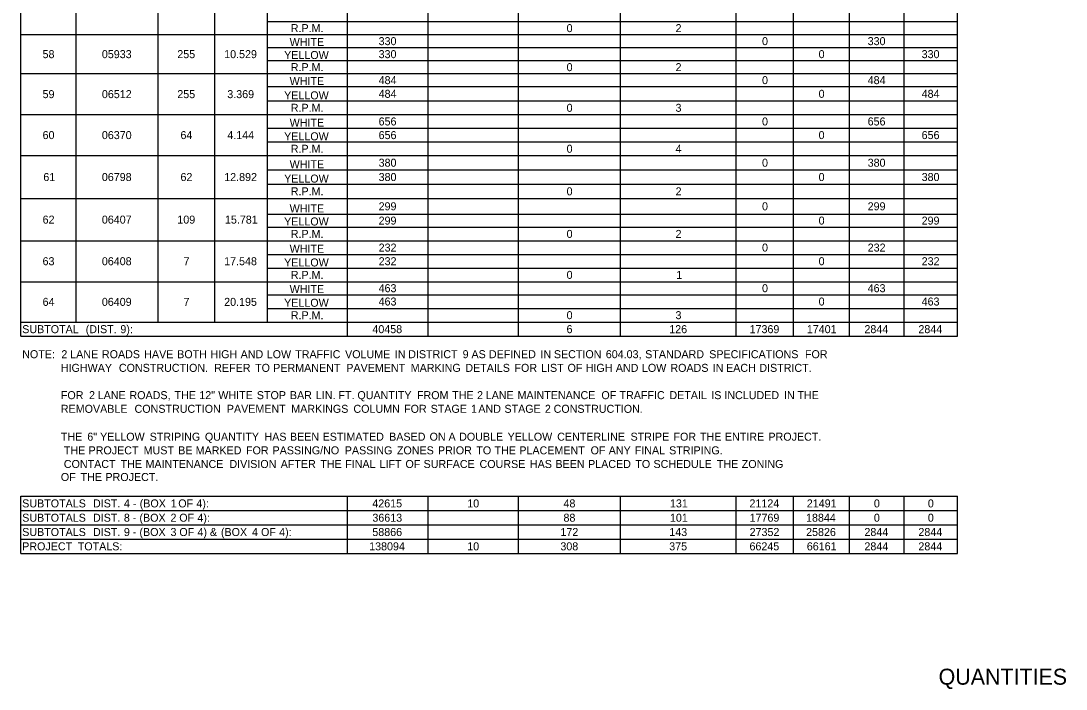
# Model space of a CAD drawing. Extents: x 544420 to 1930787, y -1947044 to 596640.
# Drawn here: x 550705 to 551489, y -1947044 to -1946543 of the extents above; entities that cross this region are included whole.
import ezdxf

# ---------------------------------------------------------------- set-up
doc = ezdxf.new("R2010")
doc.units = 0
doc.layers.add('Default', color=7, linetype='Continuous')
doc.layers.add('R_Annotation', color=7, linetype='Continuous')

msp = doc.modelspace()

# ---------------------------------------------------------------- linework, layer by layer
at = {"layer": 'Default'}
for p, q in [((550705.2, -1946779.72), (550705.2, -1946251.27)), ((550746.64, -1946769), (550746.64, -1946251.27)), ((550808.07, -1946769), (550808.07, -1946251.27)), ((550850.48, -1946769), (550850.48, -1946251.27)), ((550889.97, -1946769), (550889.97, -1946251.27)), ((550949.93, -1946779.72), (550949.93, -1946251.27)), ((551010.38, -1946779.72), (551010.38, -1946251.27)), ((551078.14, -1946779.72), (551078.14, -1946251.27)), ((551241.45, -1946779.72), (551241.45, -1946251.27)), ((551326.28, -1946779.72), (551326.28, -1946251.27)), ((551407.2, -1946779.72), (551407.2, -1946251.27)), ((551154.68, -1946779.72), (551154.68, -1946319.52)), ((551284.35, -1946779.72), (551284.35, -1946319.52)), ((551367.23, -1946779.72), (551367.23, -1946319.52)), ((550889.97, -1946543.77), (551407.2, -1946543.77)), ((550705.2, -1946553.52), (551407.2, -1946553.52)), ((550889.97, -1946563.27), (551407.2, -1946563.27)), ((550889.97, -1946573.02), (551407.2, -1946573.02)), ((550705.2, -1946582.77), (551407.2, -1946582.77)), ((550889.97, -1946592.52), (551407.2, -1946592.52)), ((550889.97, -1946603.25), (551407.2, -1946603.25)), ((550705.2, -1946613.49), (551407.2, -1946613.49)), ((550889.97, -1946623.72), (551407.2, -1946623.72)), ((550889.97, -1946633.96), (551407.2, -1946633.96)), ((550705.2, -1946644.2), (551407.2, -1946644.2)), ((550889.97, -1946654.92), (551407.2, -1946654.92)), ((550889.97, -1946665.65), (551407.2, -1946665.65)), ((550705.2, -1946676.37), (551407.2, -1946676.37)), ((550808.07, -1946769), (550808.07, -1946676.37)), ((550850.48, -1946769), (550850.48, -1946676.37)), ((550889.97, -1946769), (550889.97, -1946676.37)), ((550889.97, -1946688.07), (551407.2, -1946688.07)), ((550889.97, -1946697.82), (551407.2, -1946697.82)), ((550705.2, -1946708.06), (551407.2, -1946708.06)), ((550889.97, -1946718.3), (551407.2, -1946718.3)), ((550889.97, -1946728.54), (551407.2, -1946728.54)), ((550705.2, -1946738.77), (551407.2, -1946738.77)), ((550889.97, -1946748.52), (551407.2, -1946748.52)), ((550889.97, -1946758.76), (551407.2, -1946758.76)), ((550705.2, -1946769), (551407.2, -1946769)), ((550949.93, -1946779.72), (550949.93, -1946769)), ((551010.38, -1946779.72), (551010.38, -1946769)), ((551078.14, -1946779.72), (551078.14, -1946769)), ((551154.68, -1946779.72), (551154.68, -1946769)), ((551241.45, -1946779.72), (551241.45, -1946769)), ((551284.35, -1946779.72), (551284.35, -1946769)), ((551326.28, -1946779.72), (551326.28, -1946769)), ((551367.23, -1946779.72), (551367.23, -1946769)), ((550705.2, -1946779.72), (551407.2, -1946779.72)), ((550705.2, -1946899.65), (551407.2, -1946899.65)), ((550705.2, -1946942.55), (550705.2, -1946899.65)), ((550949.93, -1946942.55), (550949.93, -1946899.65)), ((550949.93, -1946942.55), (550949.93, -1946899.65)), ((551010.38, -1946942.55), (551010.38, -1946899.65)), ((551078.14, -1946942.55), (551078.14, -1946899.65)), ((551154.68, -1946942.55), (551154.68, -1946899.65)), ((551241.45, -1946942.55), (551241.45, -1946899.65)), ((551284.35, -1946942.55), (551284.35, -1946899.65)), ((551326.28, -1946942.55), (551326.28, -1946899.65)), ((551367.23, -1946942.55), (551367.23, -1946899.65)), ((551407.2, -1946942.55), (551407.2, -1946899.65)), ((550705.2, -1946910.37), (551407.2, -1946910.37)), ((550705.2, -1946921.1), (551407.2, -1946921.1)), ((550705.2, -1946931.82), (551407.2, -1946931.82)), ((550705.2, -1946942.55), (551407.2, -1946942.55))]:
    msp.add_line(p, q, dxfattribs=at)

# ---------------------------------------------------------------- texts
for s, p in [('R.P.M.', (550907.51, -1946551.65)), ('0', (551114.28, -1946551.65)), ('2', (551195.96, -1946551.65)), ('WHITE', (550906.67, -1946562.07)), ('330', (550973.36, -1946561.4)), ('0', (551260.77, -1946561.4)), ('330', (551339.96, -1946561.4)), ('58', (550721.45, -1946571.15)), ('05933', (550765.89, -1946571.15)), ('255', (550822.45, -1946571.15)), ('10.529', (550857.59, -1946571.15)), ('YELLOW', (550902.53, -1946571.82)), ('330', (550973.36, -1946571.15)), ('0', (551303.19, -1946571.15)), ('330', (551380.43, -1946571.15)), ('R.P.M.', (550907.51, -1946580.9)), ('0', (551114.28, -1946580.9)), ('2', (551195.96, -1946580.9)), ('WHITE', (550906.67, -1946591.32)), ('484', (550973.37, -1946590.65)), ('0', (551260.77, -1946590.65)), ('484', (551339.97, -1946590.65)), ('59', (550721.45, -1946601.13)), ('06512', (550765.92, -1946601.13)), ('255', (550822.45, -1946601.13)), ('3.369', (550859.92, -1946601.13)), ('YELLOW', (550902.53, -1946602.05)), ('484', (550973.37, -1946600.89)), ('0', (551303.19, -1946600.89)), ('484', (551380.43, -1946600.89)), ('R.P.M.', (550907.51, -1946611.37)), ('0', (551114.28, -1946611.37)), ('3', (551195.93, -1946611.37)), ('WHITE', (550906.67, -1946622.52)), ('656', (550973.35, -1946621.61)), ('0', (551260.77, -1946621.61)), ('656', (551339.95, -1946621.61)), ('60', (550721.46, -1946631.84)), ('06370', (550765.9, -1946631.84)), ('64', (550824.82, -1946631.84)), ('4.144', (550859.94, -1946631.84)), ('YELLOW', (550902.53, -1946632.76)), ('656', (550973.35, -1946631.84)), ('0', (551303.19, -1946631.84)), ('656', (551380.42, -1946631.84)), ('R.P.M.', (550907.51, -1946642.08)), ('0', (551114.28, -1946642.08)), ('4', (551195.94, -1946642.08)), ('WHITE', (550906.67, -1946653.72)), ('380', (550973.36, -1946652.56)), ('0', (551260.77, -1946652.56)), ('380', (551339.96, -1946652.56)), ('61', (550722.03, -1946663.29)), ('06798', (550765.89, -1946663.29)), ('62', (550824.83, -1946663.29)), ('12.892', (550857.63, -1946663.29)), ('YELLOW', (550902.53, -1946664.45)), ('380', (550973.36, -1946663.29)), ('0', (551303.19, -1946663.29)), ('380', (551380.43, -1946663.29)), ('R.P.M.', (550907.51, -1946674.01)), ('0', (551114.28, -1946674.01)), ('2', (551195.96, -1946674.01)), ('WHITE', (550906.67, -1946686.87)), ('299', (550973.35, -1946685.22)), ('0', (551260.77, -1946685.22)), ('299', (551339.95, -1946685.22)), ('62', (550721.48, -1946695.22)), ('06407', (550765.89, -1946695.22)), ('109', (550822.47, -1946695.22)), ('15.781', (550858.18, -1946695.22)), ('YELLOW', (550902.53, -1946696.62)), ('299', (550973.35, -1946695.95)), ('0', (551303.19, -1946695.95)), ('299', (551380.41, -1946695.95)), ('R.P.M.', (550907.51, -1946705.94)), ('0', (551114.28, -1946705.94)), ('2', (551195.96, -1946705.94)), ('WHITE', (550906.67, -1946717.1)), ('232', (550973.38, -1946716.18)), ('0', (551260.77, -1946716.18)), ('232', (551339.98, -1946716.18)), ('63', (550721.45, -1946726.42)), ('06408', (550765.89, -1946726.42)), ('7', (550827.13, -1946726.42)), ('17.548', (550857.59, -1946726.42)), ('YELLOW', (550902.53, -1946727.34)), ('232', (550973.38, -1946726.42)), ('0', (551303.19, -1946726.42)), ('232', (551380.45, -1946726.42)), ('R.P.M.', (550907.51, -1946736.66)), ('0', (551114.28, -1946736.66)), ('1', (551196.51, -1946736.66)), ('WHITE', (550906.67, -1946747.32)), ('463', (550973.35, -1946746.65)), ('0', (551260.77, -1946746.65)), ('463', (551339.95, -1946746.65)), ('64', (550721.47, -1946756.89)), ('06409', (550765.89, -1946756.89)), ('7', (550827.13, -1946756.89)), ('20.195', (550857.57, -1946756.89)), ('YELLOW', (550902.53, -1946757.56)), ('463', (550973.35, -1946756.64)), ('0', (551303.19, -1946756.64)), ('463', (551380.42, -1946756.64)), ('R.P.M.', (550907.51, -1946766.88)), ('0', (551114.28, -1946766.88)), ('3', (551195.93, -1946766.88)), ('SUBTOTAL', (550706.18, -1946777.36)), (' (DIST.', (550751.57, -1946777.36)), (' 9):', (550777.54, -1946777.36)), ('40458', (550968.69, -1946777.36)), ('6', (551114.23, -1946777.36)), ('126', (551191.22, -1946777.36)), ('17369', (551251.45, -1946777.36)), ('17401', (551294.34, -1946777.36)), ('2844', (551337.53, -1946777.36)), ('2844', (551377.99, -1946777.36)), ('NOTE:', (550706.18, -1946796.13)), ('  2', (550731.07, -1946796.13)), (' LANE', (550739.94, -1946796.13)), (' ROADS', (550763.72, -1946796.13)), (' HAVE', (550795.42, -1946796.13)), (' BOTH', (550820.14, -1946796.13)), (' HIGH', (550845.08, -1946796.13)), (' AND', (550867.69, -1946796.13)), (' LOW', (550887.27, -1946796.13)), (' TRAFFIC', (550908.6, -1946796.13)), (' VOLUME', (550945.99, -1946796.13)), (' IN', (550983.27, -1946796.13)), (' DISTRICT', (550993.3, -1946796.13)), (' 9', (551034.11, -1946796.13)), (' AS', (551040.73, -1946796.13)), (' DEFINED', (551053.8, -1946796.13)), (' IN', (551092.48, -1946796.13)), (' SECTION', (551102.51, -1946796.13)), (' 604.03,', (551141.42, -1946796.13)), (' STANDARD', (551170.95, -1946796.13)), (' SPECIFICATIONS', (551218.95, -1946796.13)), (' FOR', (551290.72, -1946796.13)), ('             HIGHWAY', (550706.18, -1946806.37)), (' CONSTRUCTION.', (550776.43, -1946806.37)), (' REFER', (550847.89, -1946806.37)), (' TO', (550878.52, -1946806.37)), (' PERMANENT', (550892.12, -1946806.37)), (' PAVEMENT', (550946.92, -1946806.37)), (' MARKING', (550995.2, -1946806.37)), (' DETAILS', (551036.13, -1946806.37)), (' FOR', (551072.96, -1946806.37)), (' LIST', (551092.88, -1946806.37)), (' OF', (551112.74, -1946806.37)), (' HIGH', (551126.32, -1946806.37)), (' AND', (551148.93, -1946806.37)), (' LOW', (551168.52, -1946806.37)), (' ROADS', (551189.84, -1946806.37)), (' IN', (551221.55, -1946806.37)), (' EACH', (551231.57, -1946806.37)), (' DISTRICT.', (551256.52, -1946806.37)), ('             FOR', (550706.18, -1946826.84)), (' 2', (550754.02, -1946826.84)), (' LANE', (550760.57, -1946826.84)), (' ROADS,', (550784.35, -1946826.84)), (' THE', (550818.07, -1946826.84)), (' 12"', (550836.72, -1946826.84)), (' WHITE', (550850.96, -1946826.84)), (' STOP', (550879.84, -1946826.84)), (' BAR', (550904.64, -1946826.84)), (' LIN.', (550924.09, -1946826.84)), (' FT.', (550941.06, -1946826.84)), (' QUANTITY', (550955.22, -1946826.84)), (' FROM', (550999.88, -1946826.84)), (' THE', (551026.25, -1946826.84)), (' 2', (551044.9, -1946826.84)), (' LANE', (551051.45, -1946826.84)), (' MAINTENANCE', (551075.23, -1946826.84)), (' OF', (551138.13, -1946826.84)), (' TRAFFIC', (551151.72, -1946826.84)), (' DETAIL', (551189.11, -1946826.84)), (' IS', (551220.49, -1946826.84)), (' INCLUDED', (551230.3, -1946826.84)), (' IN', (551275.03, -1946826.84)), (' THE', (551285.06, -1946826.84)), ('             REMOVABLE', (550706.18, -1946837.08)), (' CONSTRUCTION', (550788.17, -1946837.08)), (' PAVEMENT', (550857.35, -1946837.08)), (' MARKINGS', (550905.64, -1946837.08)), (' COLUMN', (550952.25, -1946837.08)), (' FOR', (550990.22, -1946837.08)), (' STAGE', (551010.13, -1946837.08)), (' 1', (551040.43, -1946837.08)), (' AND', (551045.88, -1946837.08)), (' STAGE', (551065.46, -1946837.08)), (' 2', (551095.76, -1946837.08)), (' CONSTRUCTION.', (551102.31, -1946837.08)), ('             THE', (550706.18, -1946857.99)), (' 6"', (550752.76, -1946857.99)), (' YELLOW', (550762.33, -1946857.99)), (' STRIPING', (550799.5, -1946857.99)), (' QUANTITY', (550840.9, -1946857.99)), (' HAS', (550885.55, -1946857.99)), (' BEEN', (550904.68, -1946857.99)), (' ESTIMATED', (550929.16, -1946857.99)), (' BASED', (550979.02, -1946857.99)), (' ON', (551009.32, -1946857.99)), (' A', (551023.54, -1946857.99)), (' DOUBLE', (551031.48, -1946857.99)), (' YELLOW', (551067.83, -1946857.99)), (' CENTERLINE', (551105, -1946857.99)), (' STRIPE', (551159.99, -1946857.99)), (' FOR', (551192.16, -1946857.99)), (' THE', (551212.07, -1946857.99)), (' ENTIRE', (551230.72, -1946857.99)), (' PROJECT.', (551263.34, -1946857.99)), ('THE', (550737.38, -1946868.22)), (' PROJECT', (550753.7, -1946868.22)), (' MUST', (550794.99, -1946868.22)), (' BE', (550820.9, -1946868.22)), (' MARKED', (550833.97, -1946868.22)), (' FOR', (550871.72, -1946868.22)), (' PASSING/NO', (550891.63, -1946868.22)), (' PASSING', (550945.76, -1946868.22)), (' ZONES', (550984.84, -1946868.22)), (' PRIOR', (551015.61, -1946868.22)), (' TO', (551044.38, -1946868.22)), (' THE', (551057.98, -1946868.22)), (' PLACEMENT', (551076.62, -1946868.22)), (' OF', (551130.03, -1946868.22)), (' ANY', (551143.62, -1946868.22)), (' FINAL', (551163.12, -1946868.22)), (' STRIPING.', (551188.91, -1946868.22)), ('CONTACT', (550737.38, -1946878.46)), (' THE', (550777.73, -1946878.46)), (' MAINTENANCE', (550796.38, -1946878.46)), (' DIVISION', (550859.28, -1946878.46)), (' AFTER', (550897.73, -1946878.46)), (' THE', (550927.43, -1946878.46)), (' FINAL', (550946.07, -1946878.46)), (' LIFT', (550971.86, -1946878.46)), (' OF', (550991.25, -1946878.46)), (' SURFACE', (551004.84, -1946878.46)), (' COURSE', (551046.78, -1946878.46)), (' HAS', (551084.54, -1946878.46)), (' BEEN', (551103.67, -1946878.46)), (' PLACED', (551128.14, -1946878.46)), (' TO', (551163.57, -1946878.46)), (' SCHEDULE', (551177.17, -1946878.46)), (' THE', (551224.7, -1946878.46)), (' ZONING', (551243.35, -1946878.46)), ('             OF', (550706.18, -1946888.21)), (' THE', (550747.7, -1946888.21)), (' PROJECT.', (550766.35, -1946888.21)), ('SUBTOTALS', (550706.18, -1946908.01)), (' DIST.', (550757, -1946908.01)), (' 4', (550780.18, -1946908.01)), (' (BOX', (550792.03, -1946908.01)), (' 1', (550815.31, -1946908.01)), (' OF', (550820.94, -1946908.01)), (' 4):', (550834.52, -1946908.01)), ('42615', (550968.63, -1946908.01)), ('10', (551039.8, -1946908.01)), ('48', (551111.94, -1946908.01)), ('131', (551191.75, -1946908.01)), ('21124', (551251.35, -1946908.01)), ('21491', (551294.34, -1946908.01)), ('0', (551344.63, -1946908.01)), ('0', (551385.09, -1946908.01)), (' -', (550786.98, -1946908.01)), ('SUBTOTALS', (550706.18, -1946918.74)), (' DIST.', (550757, -1946918.74)), (' 8', (550780.18, -1946918.74)), (' -', (550786.79, -1946918.74)), (' (BOX', (550791.85, -1946918.74)), (' 2', (550815.13, -1946918.74)), (' OF', (550821.7, -1946918.74)), (' 4):', (550835.28, -1946918.74)), ('36613', (550968.68, -1946918.74)), ('88', (551111.94, -1946918.74)), ('101', (551191.75, -1946918.74)), ('17769', (551251.45, -1946918.74)), ('18844', (551293.76, -1946918.74)), ('0', (551344.63, -1946918.74)), ('0', (551385.09, -1946918.74)), ('SUBTOTALS', (550706.18, -1946929.46)), (' DIST.', (550757, -1946929.46)), (' 9', (550780.18, -1946929.46)), (' -', (550786.78, -1946929.46)), (' (BOX', (550791.84, -1946929.46)), (' 3', (550815.12, -1946929.46)), (' OF', (550821.74, -1946929.46)), (' 4)', (550835.32, -1946929.46)), (' &', (550844.67, -1946929.46)), (' (BOX', (550852.91, -1946929.46)), (' 4', (550876.19, -1946929.46)), (' OF', (550882.99, -1946929.46)), (' 4):', (550896.57, -1946929.46)), ('58866', (550968.65, -1946929.46)), ('172', (551109.63, -1946929.46)), ('143', (551191.26, -1946929.46)), ('27352', (551251.46, -1946929.46)), ('25826', (551293.81, -1946929.46)), ('2844', (551337.53, -1946929.46)), ('2844', (551377.99, -1946929.46)), ('PROJECT', (550706.18, -1946940.19)), (' TOTALS:', (550745.6, -1946940.19)), ('138094', (550966.27, -1946940.19)), ('10', (551039.8, -1946940.19)), ('308', (551109.61, -1946940.19)), ('375', (551191.2, -1946940.19)), ('66245', (551251.38, -1946940.19)), ('66161', (551294.34, -1946940.19)), ('2844', (551337.53, -1946940.19)), ('2844', (551377.99, -1946940.19))]:
    msp.add_text(s, height=6, dxfattribs=at).set_placement(p)
at = {"layer": 'R_Annotation'}
msp.add_text('QUANTITIES', height=12, rotation=360, dxfattribs=at).set_placement((551393.15, -1947040.95))

doc.saveas('drawing.dxf')
